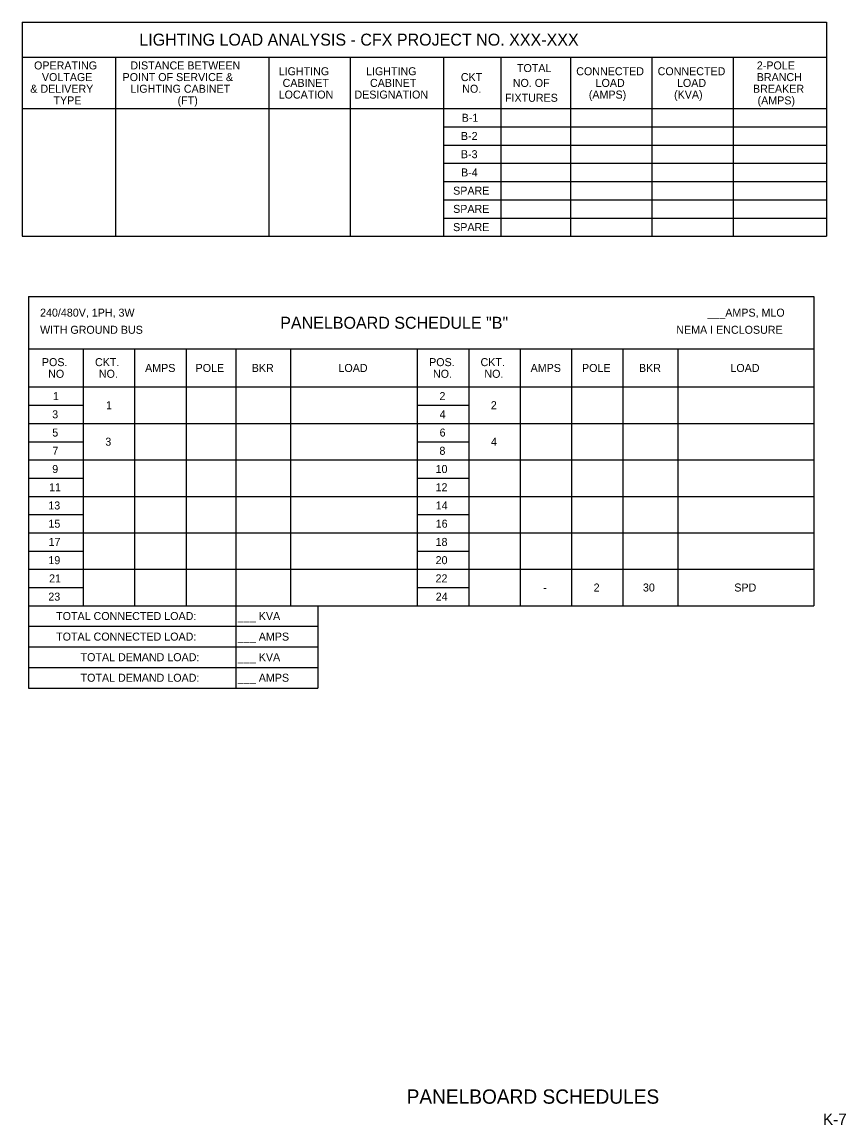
# Model space of a CAD drawing. Extents: x 856079 to 2148480, y 462635 to 2147771.
# Drawn here: x 2148473.14 to 2148480.35, y 2147761.82 to 2147771.47 of the extents above; entities that cross this region are included whole.
import ezdxf

# ---------------------------------------------------------------- set-up
doc = ezdxf.new("R2010")
doc.units = 0
for name, color, linetype in [('FLMap5', 7, 'Continuous'), ('NonPlottingEle_dp', 7, 'Continuous'), ('SignPanel', 7, 'Continuous'), ('SumBoxBorder_dp', 7, 'Continuous'), ('SumBoxLines_dp', 7, 'Continuous')]:
    doc.layers.add(name, color=color, linetype=linetype)

msp = doc.modelspace()

# ---------------------------------------------------------------- linework, layer by layer
at = {"layer": 'SumBoxBorder_dp'}
for p, q in [((2148473.1374, 2147771.4724), (2148480.1799, 2147771.4724)), ((2148473.1374, 2147771.4724), (2148473.1374, 2147769.5984)), ((2148480.1799, 2147771.4724), (2148480.1799, 2147769.5984)), ((2148473.1374, 2147771.1649), (2148480.1799, 2147771.1649)), ((2148473.1374, 2147771.1649), (2148480.1799, 2147771.1649)), ((2148473.1374, 2147769.5984), (2148480.1799, 2147769.5984)), ((2148473.1927, 2147769.0699), (2148480.0702, 2147769.0699)), ((2148473.1927, 2147769.0699), (2148473.1927, 2147765.6454)), ((2148480.0702, 2147769.0699), (2148480.0702, 2147766.3654)), ((2148473.1927, 2147768.6124), (2148480.0702, 2147768.6124)), ((2148473.1927, 2147768.6124), (2148480.0702, 2147768.6124)), ((2148473.1927, 2147766.3654), (2148480.0702, 2147766.3654)), ((2148473.1927, 2147766.3654), (2148480.0702, 2147766.3654)), ((2148475.0077, 2147766.3654), (2148475.0077, 2147765.6454)), ((2148475.7277, 2147766.3654), (2148475.7277, 2147765.6454)), ((2148475.7277, 2147766.3654), (2148475.7277, 2147765.6454)), ((2148473.1927, 2147766.1854), (2148475.7277, 2147766.1854)), ((2148473.1927, 2147766.1854), (2148475.7277, 2147766.1854)), ((2148473.1927, 2147766.0054), (2148475.7277, 2147766.0054)), ((2148473.1927, 2147766.0054), (2148475.7277, 2147766.0054)), ((2148473.1927, 2147765.8254), (2148475.7277, 2147765.8254)), ((2148473.1927, 2147765.8254), (2148475.7277, 2147765.8254)), ((2148473.1927, 2147765.6454), (2148475.7277, 2147765.6454))]:
    msp.add_line(p, q, dxfattribs=at)
at = {"layer": 'SumBoxLines_dp'}
for p, q in [((2148473.9549, 2147771.1649), (2148473.9549, 2147769.5984)), ((2148473.9549, 2147771.1649), (2148473.9549, 2147769.5984)), ((2148475.2974, 2147771.1649), (2148475.2974, 2147769.5984)), ((2148475.2974, 2147771.1649), (2148475.2974, 2147769.5984)), ((2148476.0099, 2147771.1649), (2148476.0099, 2147769.5984)), ((2148476.0099, 2147771.1649), (2148476.0099, 2147769.5984)), ((2148476.8274, 2147771.1649), (2148476.8274, 2147769.5984)), ((2148476.8274, 2147771.1649), (2148476.8274, 2147769.5984)), ((2148477.3299, 2147771.1649), (2148477.3299, 2147769.5984)), ((2148477.3299, 2147771.1649), (2148477.3299, 2147769.5984)), ((2148477.9374, 2147771.1649), (2148477.9374, 2147769.5984)), ((2148477.9374, 2147771.1649), (2148477.9374, 2147769.5984)), ((2148478.6499, 2147771.1649), (2148478.6499, 2147769.5984)), ((2148478.6499, 2147771.1649), (2148478.6499, 2147769.5984)), ((2148479.3624, 2147771.1649), (2148479.3624, 2147769.5984)), ((2148479.3624, 2147771.1649), (2148479.3624, 2147769.5984)), ((2148473.1374, 2147770.7149), (2148480.1799, 2147770.7149)), ((2148473.1374, 2147770.7149), (2148480.1799, 2147770.7149)), ((2148476.8274, 2147770.5554), (2148480.1799, 2147770.5554)), ((2148476.8274, 2147770.5554), (2148480.1799, 2147770.5554)), ((2148476.8274, 2147770.3959), (2148480.1799, 2147770.3959)), ((2148476.8274, 2147770.3959), (2148480.1799, 2147770.3959)), ((2148476.8274, 2147770.2364), (2148480.1799, 2147770.2364)), ((2148476.8274, 2147770.2364), (2148480.1799, 2147770.2364)), ((2148476.8274, 2147770.0769), (2148480.1799, 2147770.0769)), ((2148476.8274, 2147770.0769), (2148480.1799, 2147770.0769)), ((2148476.8274, 2147769.9174), (2148480.1799, 2147769.9174)), ((2148476.8274, 2147769.9174), (2148480.1799, 2147769.9174)), ((2148476.8274, 2147769.7579), (2148480.1799, 2147769.7579)), ((2148476.8274, 2147769.7579), (2148480.1799, 2147769.7579)), ((2148473.6727, 2147768.6124), (2148473.6727, 2147766.3654)), ((2148473.6727, 2147768.6124), (2148473.6727, 2147766.3654)), ((2148474.1227, 2147768.6124), (2148474.1227, 2147766.3654)), ((2148474.1227, 2147768.6124), (2148474.1227, 2147766.3654)), ((2148474.5727, 2147768.6124), (2148474.5727, 2147766.3654)), ((2148474.5727, 2147768.6124), (2148474.5727, 2147766.3654)), ((2148475.0077, 2147768.6124), (2148475.0077, 2147766.3654)), ((2148475.0077, 2147768.6124), (2148475.0077, 2147766.3654)), ((2148475.4877, 2147768.6124), (2148475.4877, 2147766.3654)), ((2148475.4877, 2147768.6124), (2148475.4877, 2147766.3654)), ((2148476.5977, 2147768.6124), (2148476.5977, 2147766.3654)), ((2148476.5977, 2147768.6124), (2148476.5977, 2147766.3654)), ((2148477.0477, 2147768.6124), (2148477.0477, 2147766.3654)), ((2148477.0477, 2147768.6124), (2148477.0477, 2147766.3654)), ((2148477.4977, 2147768.6124), (2148477.4977, 2147766.3654)), ((2148477.4977, 2147768.6124), (2148477.4977, 2147766.3654)), ((2148477.9477, 2147768.6124), (2148477.9477, 2147766.3654)), ((2148477.9477, 2147768.6124), (2148477.9477, 2147766.3654)), ((2148478.3977, 2147768.6124), (2148478.3977, 2147766.3654)), ((2148478.3977, 2147768.6124), (2148478.3977, 2147766.3654)), ((2148478.8777, 2147768.6124), (2148478.8777, 2147766.3654)), ((2148478.8777, 2147768.6124), (2148478.8777, 2147766.3654)), ((2148473.1927, 2147768.2794), (2148480.0702, 2147768.2794)), ((2148473.1927, 2147768.2794), (2148480.0702, 2147768.2794)), ((2148473.1927, 2147768.1199), (2148473.6727, 2147768.1199)), ((2148473.1927, 2147768.1199), (2148473.6727, 2147768.1199)), ((2148476.5977, 2147768.1199), (2148477.0477, 2147768.1199)), ((2148473.1927, 2147767.9604), (2148480.0702, 2147767.9604)), ((2148473.1927, 2147767.9604), (2148480.0702, 2147767.9604)), ((2148473.1927, 2147767.8009), (2148473.6727, 2147767.8009)), ((2148473.1927, 2147767.8009), (2148473.6727, 2147767.8009)), ((2148476.5977, 2147767.8009), (2148477.0477, 2147767.8009)), ((2148476.5977, 2147767.8009), (2148477.0477, 2147767.8009)), ((2148473.1927, 2147767.6414), (2148476.5977, 2147767.6414)), ((2148473.1927, 2147767.6414), (2148480.0702, 2147767.6414)), ((2148477.0477, 2147767.6414), (2148480.0702, 2147767.6414)), ((2148473.1927, 2147767.4819), (2148473.6727, 2147767.4819)), ((2148473.1927, 2147767.4819), (2148473.6727, 2147767.4819)), ((2148476.5977, 2147767.4819), (2148477.0477, 2147767.4819)), ((2148476.5977, 2147767.4819), (2148477.0477, 2147767.4819)), ((2148473.1927, 2147767.3224), (2148480.0702, 2147767.3224)), ((2148473.1927, 2147767.3224), (2148480.0702, 2147767.3224)), ((2148473.1927, 2147767.1629), (2148473.6727, 2147767.1629)), ((2148473.1927, 2147767.1629), (2148473.6727, 2147767.1629)), ((2148476.5977, 2147767.1629), (2148477.0477, 2147767.1629)), ((2148473.1927, 2147767.0034), (2148480.0702, 2147767.0034)), ((2148473.1927, 2147767.0034), (2148480.0702, 2147767.0034)), ((2148473.1927, 2147766.8439), (2148473.6727, 2147766.8439)), ((2148473.1927, 2147766.8439), (2148473.6727, 2147766.8439)), ((2148476.5977, 2147766.8439), (2148477.0477, 2147766.8439)), ((2148476.5977, 2147766.8439), (2148477.0477, 2147766.8439)), ((2148473.1927, 2147766.6844), (2148476.5977, 2147766.6844)), ((2148473.1927, 2147766.6844), (2148480.0702, 2147766.6844)), ((2148477.0477, 2147766.6844), (2148480.0702, 2147766.6844)), ((2148473.1927, 2147766.5249), (2148473.6727, 2147766.5249)), ((2148473.1927, 2147766.5249), (2148473.6727, 2147766.5249)), ((2148476.5977, 2147766.5249), (2148477.0477, 2147766.5249)), ((2148476.5977, 2147766.5249), (2148477.0477, 2147766.5249))]:
    msp.add_line(p, q, dxfattribs=at)

# ---------------------------------------------------------------- texts
at = {"layer": 'FLMap5'}
for s, height, p in [('LIGHTING LOAD ANALYSIS - CFX PROJECT NO. XXX-XXX', 0.105, (2148474.1638, 2147771.2662)), ('OPERATING', 0.07, (2148473.2425, 2147771.0579)), ('DISTANCE BETWEEN', 0.07, (2148474.0854, 2147771.0579)), ('LIGHTING', 0.07, (2148475.3839, 2147771.0069)), ('LIGHTING', 0.07, (2148476.1489, 2147771.0069)), ('TOTAL', 0.07, (2148477.47, 2147771.0349)), ('CONNECTED', 0.07, (2148477.989, 2147771.0069)), ('CONNECTED', 0.07, (2148478.7015, 2147771.0069)), ('2-POLE', 0.07, (2148479.5701, 2147771.0579)), ('VOLTAGE', 0.07, (2148473.3112, 2147770.9559)), ('POINT OF SERVICE &', 0.07, (2148474.0176, 2147770.9559)), ('CABINET', 0.07, (2148475.4183, 2147770.9049)), ('CABINET', 0.07, (2148476.1833, 2147770.9049)), ('CKT', 0.07, (2148476.9788, 2147770.9559)), ('NO. OF', 0.07, (2148477.4336, 2147770.9049)), ('LOAD', 0.07, (2148478.1584, 2147770.9049)), ('LOAD', 0.07, (2148478.8709, 2147770.9049)), ('BRANCH', 0.07, (2148479.5692, 2147770.9559)), ('& DELIVERY', 0.07, (2148473.2097, 2147770.8539)), ('LIGHTING CABINET', 0.07, (2148474.0859, 2147770.8539)), ('NO.', 0.07, (2148476.991, 2147770.8539)), ('(AMPS)', 0.07, (2148478.099, 2147770.8029)), ('(KVA)', 0.07, (2148478.8454, 2147770.8029)), ('BREAKER', 0.07, (2148479.5362, 2147770.8539)), ('TYPE', 0.07, (2148473.4128, 2147770.7519)), ('(FT)', 0.07, (2148474.4993, 2147770.7519)), ('LOCATION', 0.07, (2148475.3839, 2147770.8029)), ('DESIGNATION', 0.07, (2148476.0473, 2147770.8029)), ('FIXTURES', 0.07, (2148477.365, 2147770.7749)), ('(AMPS)', 0.07, (2148479.5765, 2147770.7519)), ('B-1', 0.07, (2148476.9862, 2147770.6002)), ('B-2', 0.07, (2148476.9795, 2147770.4407)), ('B-3', 0.07, (2148476.9794, 2147770.2812)), ('B-4', 0.07, (2148476.9808, 2147770.1217)), ('SPARE', 0.07, (2148476.9115, 2147769.9622)), ('SPARE', 0.07, (2148476.9115, 2147769.8027)), ('SPARE', 0.07, (2148476.9115, 2147769.6432)), ('240/480V, 1PH, 3W', 0.07, (2148473.2952, 2147768.8949)), ('___AMPS, MLO', 0.07, (2148479.1374, 2147768.8949)), ('PANELBOARD SCHEDULE "B"', 0.105, (2148475.3974, 2147768.7887)), ('WITH GROUND BUS', 0.07, (2148473.2952, 2147768.7449)), ('NEMA I ENCLOSURE', 0.07, (2148478.865, 2147768.7449)), ('POS.', 0.07, (2148473.3112, 2147768.4619)), ('CKT.', 0.07, (2148473.7762, 2147768.4619)), ('AMPS', 0.07, (2148474.2146, 2147768.4109)), ('POLE', 0.07, (2148474.6569, 2147768.4109)), ('BKR', 0.07, (2148475.1482, 2147768.4109)), ('LOAD', 0.07, (2148475.9075, 2147768.4109)), ('POS.', 0.07, (2148476.7012, 2147768.4619)), ('CKT.', 0.07, (2148477.1512, 2147768.4619)), ('AMPS', 0.07, (2148477.5896, 2147768.4109)), ('POLE', 0.07, (2148478.0394, 2147768.4109)), ('BKR', 0.07, (2148478.5382, 2147768.4109)), ('LOAD', 0.07, (2148479.3387, 2147768.4109)), ('NO', 0.07, (2148473.3659, 2147768.3599)), ('NO.', 0.07, (2148473.81, 2147768.3599)), ('NO.', 0.07, (2148476.735, 2147768.3599)), ('NO.', 0.07, (2148477.185, 2147768.3599)), ('1', 0.07, (2148473.408, 2147768.1647)), ('2', 0.07, (2148476.7913, 2147768.1647)), ('1', 0.07, (2148473.873, 2147768.0849)), ('2', 0.07, (2148477.2413, 2147768.0849)), ('3', 0.07, (2148473.4013, 2147768.0052)), ('4', 0.07, (2148476.7927, 2147768.0052)), ('5', 0.07, (2148473.4022, 2147767.8457)), ('6', 0.07, (2148476.7927, 2147767.8457)), ('3', 0.07, (2148473.8663, 2147767.7659)), ('4', 0.07, (2148477.2427, 2147767.7659)), ('7', 0.07, (2148473.4033, 2147767.6862)), ('8', 0.07, (2148476.7915, 2147767.6862)), ('9', 0.07, (2148473.4017, 2147767.5267)), ('10', 0.07, (2148476.758, 2147767.5267)), ('11', 0.07, (2148473.3742, 2147767.3672)), ('12', 0.07, (2148476.7574, 2147767.3672)), ('13', 0.07, (2148473.3674, 2147767.2077)), ('14', 0.07, (2148476.7588, 2147767.2077)), ('15', 0.07, (2148473.3683, 2147767.0482)), ('16', 0.07, (2148476.7588, 2147767.0482)), ('17', 0.07, (2148473.3694, 2147766.8887)), ('18', 0.07, (2148476.7577, 2147766.8887)), ('19', 0.07, (2148473.3678, 2147766.7292)), ('20', 0.07, (2148476.758, 2147766.7292)), ('21', 0.07, (2148473.3742, 2147766.5697)), ('22', 0.07, (2148476.7574, 2147766.5697)), ('2', 0.07, (2148478.1413, 2147766.4899)), ('30', 0.07, (2148478.573, 2147766.4899)), ('SPD', 0.07, (2148479.3726, 2147766.4899)), ('23', 0.07, (2148473.3674, 2147766.4102)), ('24', 0.07, (2148476.7588, 2147766.4102)), ('-', 0.07, (2148477.6992, 2147766.4899)), ('TOTAL CONNECTED LOAD:', 0.07, (2148473.4358, 2147766.2404)), ('___ KVA', 0.07, (2148475.0277, 2147766.2404)), ('TOTAL CONNECTED LOAD:', 0.07, (2148473.4358, 2147766.0604)), ('___ AMPS', 0.07, (2148475.0277, 2147766.0604)), ('TOTAL DEMAND LOAD:', 0.07, (2148473.6498, 2147765.8804)), ('___ KVA', 0.07, (2148475.0277, 2147765.8804)), ('TOTAL DEMAND LOAD:', 0.07, (2148473.6498, 2147765.7004)), ('___ AMPS', 0.07, (2148475.0277, 2147765.7004))]:
    msp.add_text(s, height=height, dxfattribs=at).set_placement(p)
at = {"layer": 'NonPlottingEle_dp'}
msp.add_text('K-7', height=0.1, dxfattribs=at).set_placement((2148480.1488, 2147761.8225))
at = {"layer": 'SignPanel'}
msp.add_text('     PANELBOARD SCHEDULES      ', height=0.125, dxfattribs=at).set_placement((2148476.272, 2147762.0082))

doc.saveas('drawing.dxf')
